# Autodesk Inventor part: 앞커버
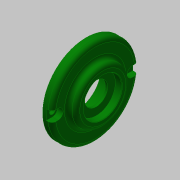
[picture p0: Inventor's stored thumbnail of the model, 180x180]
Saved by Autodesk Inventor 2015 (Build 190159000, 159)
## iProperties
Created: 2019-06
Part Number: 앞커버
Material: 알루미늄 6061
Document SubType Name: Modeling
Designer: mduedu
Density: 1 g/cm^3
Appearance: 진녹색
Author: mduedu
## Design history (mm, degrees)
sketch "스케치1"
  geometry: L1 (0, 0)-(7, 0); L2 (7, 0)-(7, 25); L3 (7, 25)-(0, 25); L4 (0, 25)-(0, 0); L5 (7, 0)-(14, 0); L6 (14, 0)-(14, 34); L7 (14, 34)-(7, 34); L8 (7, 34)-(7, 0); L9 (14, 0)-(20, 0); L10 (20, 0)-(20, 21); L11 (20, 21)-(14, 21); L12 (14, 21)-(14, 0)
  constraints: 24 end point, 6 parallel, 3 horizontal, 3 perpendicular
  dimensions: "d0" = 20 distance between parallel lines of L10 L4; "d2" = 7 distance of L2.end L3.end; "d3" = 7 distance of L6.end L7.end; "d4" = 50 diameter of L3 L1; "d5" = 68 diameter of L7 L5; "d6" = 42 diameter of L11 L9
revolve "회전1" sketch "스케치1" stored, may be unused: angle "d7" = 90 deg
sketch "스케치2"
  geometry: L1 (0, -25)-(0, 25) reference; L2 (0, 25)-(7, 25) reference; L3 (7, 25)-(7, 34) reference; L4 (7, 34)-(14, 34) reference; L5 (14, 34)-(14, 21) reference; L6 (14, 21)-(20, 21) reference; L7 (20, 21)-(20, -21) reference; L8 (20, -21)-(14, -21) reference; L9 (14, -21)-(14, -34) reference; L10 (14, -34)-(7, -34) reference; L11 (7, -34)-(7, -25) reference; L12 (7, -25)-(0, -25) reference; L13 (10, 0)-(10, 17.5); L14 (10, 17.5)-(0, 17.5); L15 (0, 17.5)-(0, 0); L16 (13, 0)-(13, 15); L17 (13, 15)-(10, 15); L18 (10, 15)-(10, 0); L19 (14.8, 0)-(14.8, 9); L20 (14.8, 9)-(13, 9); L21 (13, 9)-(13, 0); L22 (20, 0)-(20, 15); L23 (20, 15)-(14.8, 15); L24 (14.8, 15)-(14.8, 0)
  constraints: 24 end point, 4 horizontal, 4 horizontal alignment, 4 parallel, 4 vertical, 1 point on line, 8 other
  dimensions: "d8" = 35 dimension on L14; "d10" = 30 dimension on L17; "d11" = 18 dimension on L20; "d12" = 30 dimension on L23; "d13" = 10 distance of L13.end L14.end; "d14" = 3 distance of L16.end L17.end; "d15" = 5.2 distance of L22.end L23.end
revolve "회전2" sketch "스케치2" stored, may be unused: angle "d16" = 90 deg
chamfer "모따기1" distance "d18" = 0.5; stored, may be unused: second distance "d19" = 2, angle "d20" = 30 deg
fillet "모깎기2" dims "d21" = 0.3
fillet "모깎기3" dims "d22" = 3
chamfer "모따기2" distance "d23" = 1; stored, may be unused: second distance "d24" = 2, angle "d25" = 30 deg
fillet "모깎기4" dims "d26" = 3
sketch "스케치3" dims "d27" = 58
  geometry: L1 (-4, 29)-(-4, 33.764); L2 (4, 33.764)-(4, 29); A1 r 4 centre (0, 29) between (-4, 29) and (4, 29); A2 r 34 centre (0, 0) between (4, 33.764) and (-4, 33.764); A3 r 34 centre (0, 0) between (4, 33.764) and (-4, 33.764) reference; 3 further points
  constraints: 6 point on circle, 4 end point, 3 coincident, 2 centre point, 2 tangent, 2 vertical, 2 vertical alignment, 1 concentric, 2 other
  dimensions: "d28" = 8 diameter of A1
extrude "돌출1" cut sketch "스케치3" distance "d29" = 4.4; taper "d30" = 0 deg
sketch "스케치4"
  geometry: A1 r 4 centre (0, 29) between (-4, 29) and (4, 29) reference; 2 further points
  constraints: 1 coincident
hole "구멍1" sketch "스케치4" at (0, 29) diameter "d34" = 4.5; stored, may be unused: countersink angle "d38" = 90 deg, drill point angle "d40" = 118 deg; dims "d35" = 6, "d36" = 4, "d37" = 2, "d39" = 8
node "솔리드1"
pattern_circular "원형 패턴1" dims angle "d32" = 360 deg
pattern_circular "원형 패턴2" dims angle "d42" = 360 deg
node "절단 모서리 투영1"
